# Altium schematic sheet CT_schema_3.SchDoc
size 276 x 169 mm
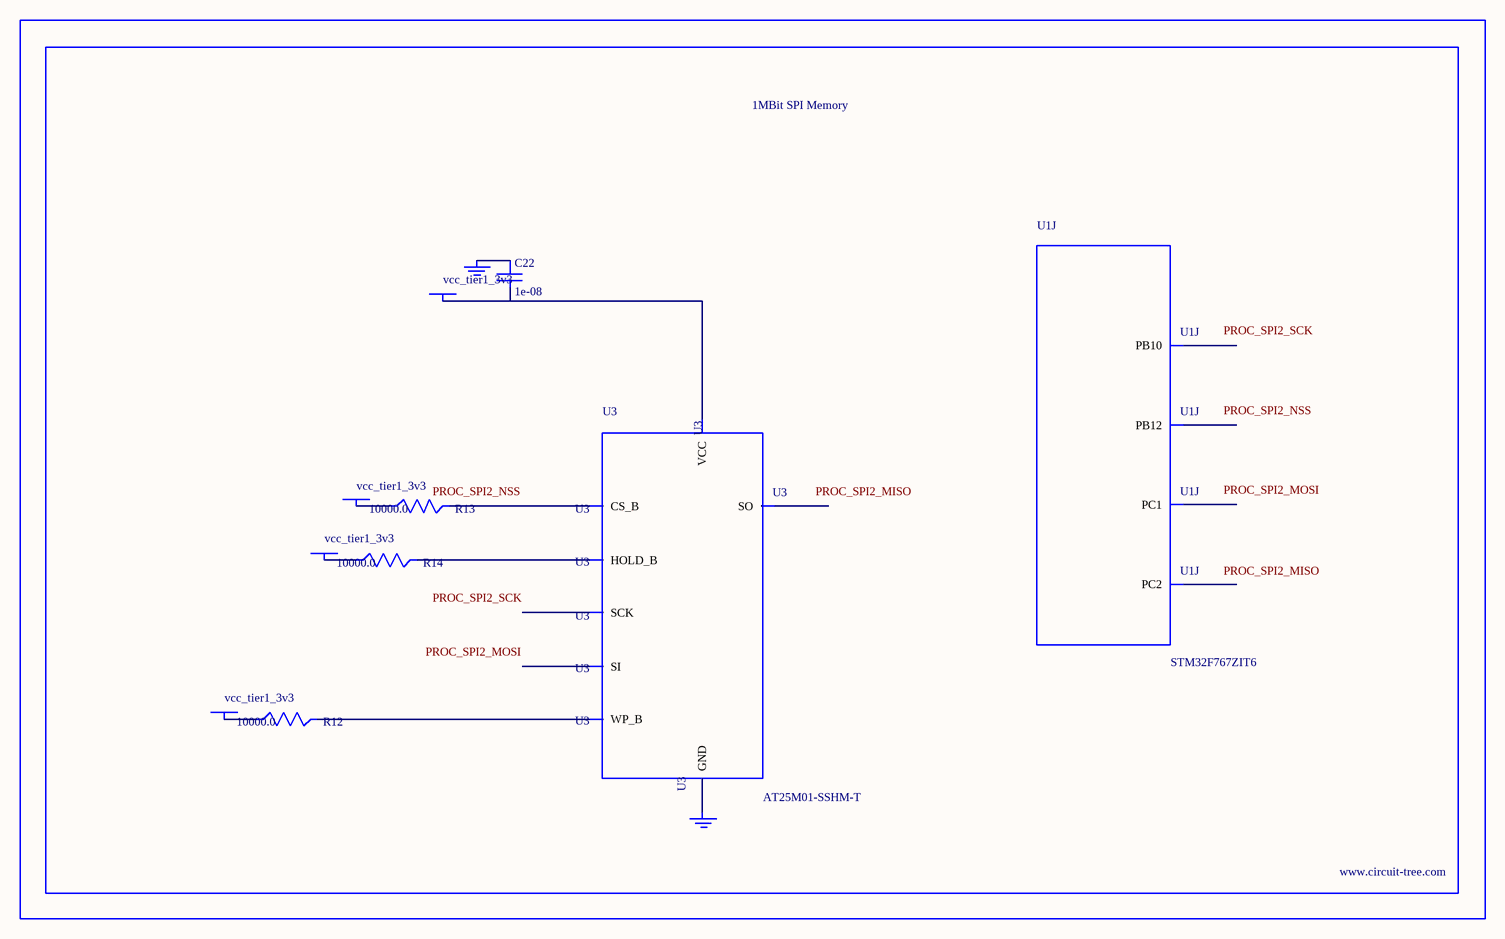
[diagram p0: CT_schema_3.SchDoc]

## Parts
BORDER2  (no value)
C22  1e-08  [C0402]
GND_INSTANCE_2_0  (no value)
GND_INSTANCE_2_1  (no value)
POWER_INSTANCE_2_0  vcc_tier1_3v3
POWER_INSTANCE_2_1  vcc_tier1_3v3
POWER_INSTANCE_2_2  vcc_tier1_3v3
POWER_INSTANCE_2_3  vcc_tier1_3v3
R12  10000.0  [R0603]
R13  10000.0  [R0603]
R14  10000.0  [R0603]
U1  STM32F767ZIT6  [LQFP144]  (part J of 13)
U3  AT25M01-SSHM-T  [SOIC-8]

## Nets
NetC22_1: C22.1 GND_INSTANCE_2_0.0(GND)
NetC22_2: C22.2 POWER_INSTANCE_2_3.0(PWR) U3.8(VCC)
NetGND_INSTANCE_2_1_0: GND_INSTANCE_2_1.0(GND) U3.4(GND)
NetPOWER_INSTANCE_2_0_0: POWER_INSTANCE_2_0.0(PWR) R13.1
NetPOWER_INSTANCE_2_1_0: POWER_INSTANCE_2_1.0(PWR) R12.1
NetPOWER_INSTANCE_2_2_0: POWER_INSTANCE_2_2.0(PWR) R14.1
NetR12_2: R12.2 U3.3(WP_B)
NetR13_2: R13.2 U3.1(CS_B)
NetR14_2: R14.2 U3.7(HOLD_B)

Not connected (* = marked no-connect by the designer): U1 27(PC1) 28(PC2) 69(PB10) 73(PB12); U3 2(SO) 5(SI) 6(SCK)

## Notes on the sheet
- Labels drawn without touching a wire or pin: PROC_SPI2_MISO, PROC_SPI2_MOSI, PROC_SPI2_NSS, PROC_SPI2_SCK

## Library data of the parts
BORDER2 = BORDER_PAGE2
C22 = C0402C103K3RAC
GND_INSTANCE_2_0 GND_INSTANCE_2_1 = GND
POWER_INSTANCE_2_0-POWER_INSTANCE_2_3 = PWR
R12-R14 = RC0603JR-0710KL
